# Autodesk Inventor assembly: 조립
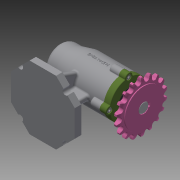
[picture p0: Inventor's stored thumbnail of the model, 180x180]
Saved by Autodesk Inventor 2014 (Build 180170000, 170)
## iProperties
Created: 2021-01
Part Number: 조립
Document SubType Name: Assembly
Designer: kh
Author: kh
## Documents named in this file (12)
- C:\Users\kh\Desktop\710106V1022\조립.iam
- C:\Users\kh\Desktop\710106V1022\본체.ipt
- C:\Users\kh\Desktop\710106V1022\멈춤나사 M3.ipt
- C:\Users\kh\Desktop\710106V1022\베어링 6004.ipt
- C:\Users\kh\Desktop\710106V1022\베어링 51202.ipt
- C:\Users\kh\Desktop\710106V1022\볼트 M4.ipt
- C:\Users\kh\Desktop\710106V1022\스프로킷.ipt
- C:\Users\kh\Desktop\710106V1022\어댑터슬리브.ipt
- C:\Users\kh\Desktop\710106V1022\오일 실.ipt
- C:\Users\kh\Desktop\710106V1022\축.ipt
- C:\Users\kh\Desktop\710106V1022\커버.ipt
- C:\Users\kh\Desktop\710106V1022\키 5 x 5 x 14.ipt
